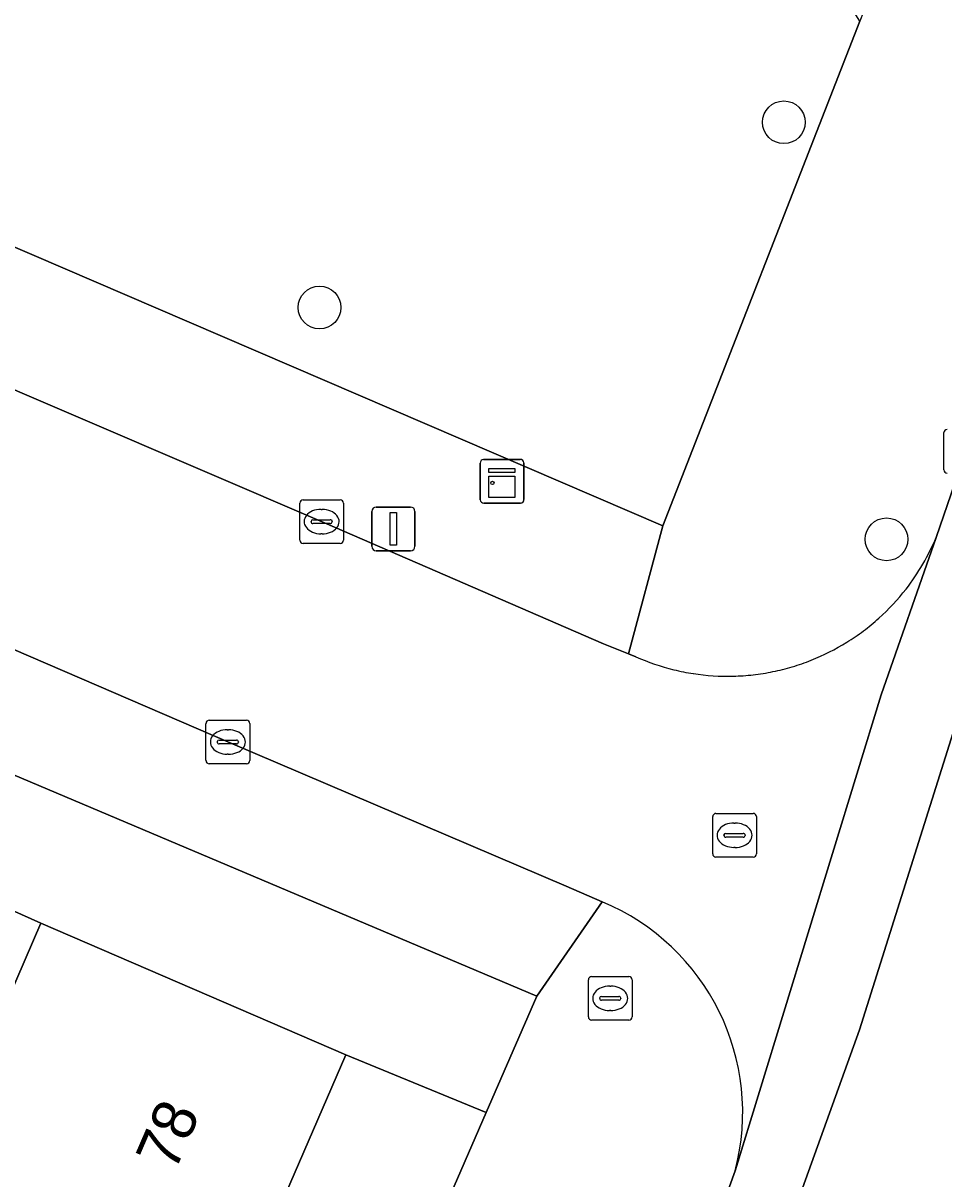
# Model space of a CAD drawing. Extents: x 162803 to 163818, y 381639 to 382475.
# Drawn here: x 163434.41 to 163455.49, y 382015.39 to 382041.86 of the extents above; entities that cross this region are included whole.
import ezdxf

# ---------------------------------------------------------------- set-up
doc = ezdxf.new("R2010")
doc.units = 0
for name, color, linetype in [('IMGEO_Boom', 7, 'Continuous'), ('IMGEO_Brandkraan', 7, 'Continuous'), ('IMGEO_Erf', 7, 'Continuous'), ('IMGEO_Groenvoorziening', 7, 'Continuous'), ('IMGEO_Haag', 7, 'Continuous'), ('IMGEO_Kast', 7, 'Continuous'), ('IMGEO_Kolk', 7, 'Continuous'), ('IMGEO_Lichtmast', 7, 'Continuous'), ('IMGEO_Pand', 7, 'Continuous'), ('IMGEO_Pand_nummerreeks', 7, 'Continuous'), ('IMGEO_Rijbaan_lokaal_gesloten', 7, 'Continuous'), ('IMGEO_Rijbaan_lokaal_open', 7, 'Continuous'), ('IMGEO_Rioolput', 7, 'Continuous'), ('IMGEO_Voetpad_open', 7, 'Continuous')]:
    doc.layers.add(name, color=color, linetype=linetype)

msp = doc.modelspace()

# ---------------------------------------------------------------- linework, layer by layer
at = {"layer": 'IMGEO_Boom'}
for centre in [(163451.822, 382039.591), (163441.195, 382035.351), (163454.174, 382030.04)]:
    msp.add_circle(centre, 0.489, dxfattribs=at)
at = {"layer": 'IMGEO_Brandkraan'}
for p, q in [((163447.348, 382019.102), (163447.348, 382019.954)), ((163447.423, 382020.028), (163448.275, 382020.028)), ((163448.349, 382019.954), (163448.349, 382019.102)), ((163447.836, 382019.808), (163447.861, 382019.808)), ((163447.607, 382019.522), (163447.607, 382019.534)), ((163448.045, 382019.485), (163447.647, 382019.485)), ((163447.65, 382019.571), (163448.048, 382019.571)), ((163448.091, 382019.534), (163448.091, 382019.522)), ((163447.859, 382019.248), (163447.834, 382019.248)), ((163448.275, 382019.028), (163447.423, 382019.028))]:
    msp.add_line(p, q, dxfattribs=at)
for points in [[(163447.348, 382019.102), (163447.348, 382019.954)], [(163447.423, 382020.028), (163448.275, 382020.028)], [(163448.349, 382019.954), (163448.349, 382019.102)], [(163448.275, 382019.028), (163447.423, 382019.028)]]:
    msp.add_lwpolyline(points, dxfattribs=at)
for centre, radius, start, end in [((163447.425, 382019.952), 0.0765, 91.552, 178.448), ((163447.425, 382019.952), 0.0765, 91.552, 178.448), ((163448.273, 382019.952), 0.0765, 1.552, 88.448), ((163448.273, 382019.952), 0.0765, 1.552, 88.448), ((163447.647, 382019.531), 0.0403, 85.8775, 175.7526), ((163447.644, 382019.521), 0.0366, 178.938, 274.7102), ((163448.048, 382019.528), 0.043, 264.8664, 352.4533), ((163448.052, 382019.533), 0.0386, 1.7309, 96.639), ((163447.425, 382019.104), 0.0765, 181.552, 268.448), ((163447.425, 382019.104), 0.0765, 181.552, 268.448), ((163448.273, 382019.104), 0.0765, 271.552, 358.448), ((163448.273, 382019.104), 0.0765, 271.552, 358.448)]:
    msp.add_arc(centre, radius, start, end, dxfattribs=at)
for centre, major_axis, ratio, start_param, end_param in [((163447.835, 382019.528), (-0.387, 0.002), 0.722429, 4.712389, 7.853982), ((163447.86, 382019.528), (-0.39, 0.002), 0.717154, 1.570796, 4.712389)]:
    msp.add_ellipse(centre, major_axis=major_axis, ratio=ratio, start_param=start_param, end_param=end_param, dxfattribs=at)
at = {"layer": 'IMGEO_Erf'}
for points in [[(163432.155, 382015.101), (163434.813, 382021.25), (163423.919, 382026.134)], [(163415.261, 381948.361), (163437.67, 382000), (163445.009, 382016.913), (163441.794, 382018.234), (163439.136, 382012.084), (163436.568, 382006.144), (163434.146, 382000.54)]]:
    msp.add_lwpolyline(points, dxfattribs=at)
at = {"layer": 'IMGEO_Groenvoorziening'}
for points in [[(163425.697, 382054.699), (163420.454, 382042.652), (163428.107, 382039.359), (163438.211, 382035.013), (163449.05, 382030.35), (163453.565, 382041.904), (163452.311, 382043.913), (163447.838, 382051.076), (163440.6, 382054.08), (163438.716, 382049.427), (163433.421, 382051.571)], [(163425.146, 382028.468), (163423.919, 382026.134), (163434.813, 382021.25), (163441.794, 382018.234), (163445.009, 382016.913), (163446.165, 382019.577)]]:
    msp.add_lwpolyline(points, close=True, dxfattribs=at)
at = {"layer": 'IMGEO_Haag'}
msp.add_lwpolyline([(163425.146, 382028.468), (163423.919, 382026.134), (163434.813, 382021.25), (163441.794, 382018.234), (163445.009, 382016.913), (163446.165, 382019.577)], close=True, dxfattribs=at)
at = {"layer": 'IMGEO_Kast'}
for p, q in [((163444.873, 382030.944), (163444.873, 382031.785)), ((163444.873, 382031.785), (163444.873, 382030.944)), ((163444.948, 382031.869), (163445.789, 382031.869)), ((163445.789, 382031.869), (163444.948, 382031.869)), ((163445.873, 382031.794), (163445.873, 382030.953)), ((163445.873, 382030.953), (163445.873, 382031.794)), ((163445.798, 382030.869), (163444.957, 382030.869)), ((163444.957, 382030.869), (163445.798, 382030.869))]:
    msp.add_line(p, q, dxfattribs=at)
for points in [[(163445.068, 382031.659), (163445.668, 382031.659), (163445.668, 382031.574), (163445.068, 382031.574), (163445.068, 382031.659)], [(163445.068, 382031.484), (163445.668, 382031.484), (163445.668, 382030.995), (163445.068, 382030.995), (163445.068, 382031.484)]]:
    msp.add_lwpolyline(points, dxfattribs=at)
msp.add_circle((163445.152, 382031.333), 0.0377, dxfattribs=at)
for centre, start, end in [((163444.951, 382031.791), 92.4484, 184.2845), ((163444.951, 382031.791), 92.4484, 184.2845), ((163445.795, 382031.791), 2.4484, 94.2845), ((163445.795, 382031.791), 2.4484, 94.2845), ((163444.951, 382030.947), 182.4484, 274.2845), ((163444.951, 382030.947), 182.4484, 274.2845), ((163445.795, 382030.947), 272.4484, 4.2845), ((163445.795, 382030.947), 272.4484, 4.2845)]:
    msp.add_arc(centre, 0.0779, start, end, dxfattribs=at)
at = {"layer": 'IMGEO_Kolk'}
for p, q in [((163455.486, 382031.631), (163455.486, 382032.483)), ((163440.741, 382030.02), (163440.741, 382030.872)), ((163440.816, 382030.946), (163441.668, 382030.946)), ((163441.229, 382030.726), (163441.254, 382030.726)), ((163441.742, 382030.872), (163441.742, 382030.02)), ((163441.043, 382030.489), (163441.441, 382030.489)), ((163441, 382030.44), (163441, 382030.452)), ((163441.438, 382030.403), (163441.04, 382030.403)), ((163441.484, 382030.452), (163441.484, 382030.44)), ((163441.668, 382029.946), (163440.816, 382029.946)), ((163441.252, 382030.166), (163441.227, 382030.166)), ((163438.595, 382024.973), (163438.595, 382025.825)), ((163438.67, 382025.899), (163439.522, 382025.899)), ((163439.596, 382025.825), (163439.596, 382024.973)), ((163438.897, 382025.442), (163439.295, 382025.442)), ((163439.083, 382025.679), (163439.108, 382025.679)), ((163438.854, 382025.393), (163438.854, 382025.405)), ((163439.292, 382025.356), (163438.894, 382025.356)), ((163439.338, 382025.405), (163439.338, 382025.393)), ((163439.522, 382024.899), (163438.67, 382024.899)), ((163439.106, 382025.119), (163439.081, 382025.119))]:
    msp.add_line(p, q, dxfattribs=at)
for points in [[(163455.486, 382031.631), (163455.486, 382032.483)], [(163440.741, 382030.02), (163440.741, 382030.872)], [(163440.816, 382030.946), (163441.668, 382030.946)], [(163441.742, 382030.872), (163441.742, 382030.02)], [(163441.668, 382029.946), (163440.816, 382029.946)], [(163438.595, 382024.973), (163438.595, 382025.825)], [(163438.67, 382025.899), (163439.522, 382025.899)], [(163439.596, 382025.825), (163439.596, 382024.973)], [(163439.522, 382024.899), (163438.67, 382024.899)]]:
    msp.add_lwpolyline(points, dxfattribs=at)
for centre, radius, start, end in [((163455.563, 382032.481), 0.0765, 91.552, 178.448), ((163455.563, 382032.481), 0.0765, 91.552, 178.448), ((163455.563, 382031.633), 0.0765, 181.552, 268.448), ((163455.563, 382031.633), 0.0765, 181.552, 268.448), ((163440.818, 382030.87), 0.0765, 91.552, 178.448), ((163440.818, 382030.87), 0.0765, 91.552, 178.448), ((163441.666, 382030.87), 0.0765, 1.552, 88.448), ((163441.666, 382030.87), 0.0765, 1.552, 88.448), ((163441.04, 382030.449), 0.0403, 85.8775, 175.7526), ((163441.445, 382030.451), 0.0386, 1.7309, 96.639), ((163441.037, 382030.439), 0.0366, 178.938, 274.7102), ((163441.441, 382030.446), 0.043, 264.8664, 352.4533), ((163440.818, 382030.022), 0.0765, 181.552, 268.448), ((163440.818, 382030.022), 0.0765, 181.552, 268.448), ((163441.666, 382030.022), 0.0765, 271.552, 358.448), ((163441.666, 382030.022), 0.0765, 271.552, 358.448), ((163438.672, 382025.823), 0.0765, 91.552, 178.448), ((163438.672, 382025.823), 0.0765, 91.552, 178.448), ((163439.52, 382025.823), 0.0765, 1.552, 88.448), ((163439.52, 382025.823), 0.0765, 1.552, 88.448), ((163438.894, 382025.402), 0.0403, 85.8775, 175.7526), ((163439.299, 382025.404), 0.0386, 1.7309, 96.639), ((163438.891, 382025.392), 0.0366, 178.938, 274.7102), ((163439.295, 382025.399), 0.043, 264.8664, 352.4533), ((163438.672, 382024.975), 0.0765, 181.552, 268.448), ((163438.672, 382024.975), 0.0765, 181.552, 268.448), ((163439.52, 382024.975), 0.0765, 271.552, 358.448), ((163439.52, 382024.975), 0.0765, 271.552, 358.448)]:
    msp.add_arc(centre, radius, start, end, dxfattribs=at)
for centre, major_axis, ratio, start_param, end_param in [((163441.228, 382030.446), (-0.387, 0.002), 0.722429, 4.712389, 7.853982), ((163441.253, 382030.446), (-0.39, 0.002), 0.717154, 1.570796, 4.712389), ((163439.082, 382025.399), (-0.387, 0.002), 0.722429, 4.712389, 7.853982), ((163439.107, 382025.399), (-0.39, 0.002), 0.717154, 1.570796, 4.712389)]:
    msp.add_ellipse(centre, major_axis=major_axis, ratio=ratio, start_param=start_param, end_param=end_param, dxfattribs=at)
at = {"layer": 'IMGEO_Lichtmast'}
for p, q in [((163442.489, 382030.78), (163443.279, 382030.78)), ((163443.279, 382030.78), (163442.489, 382030.78)), ((163442.389, 382029.88), (163442.389, 382030.68)), ((163442.389, 382030.68), (163442.389, 382029.88)), ((163443.379, 382030.68), (163443.379, 382029.88)), ((163443.379, 382029.88), (163443.379, 382030.68)), ((163443.279, 382029.78), (163442.489, 382029.78)), ((163442.489, 382029.78), (163443.279, 382029.78))]:
    msp.add_line(p, q, dxfattribs=at)
msp.add_lwpolyline([(163442.809, 382030.655), (163442.959, 382030.655), (163442.959, 382029.905), (163442.809, 382029.905), (163442.809, 382030.655)], dxfattribs=at)
for centre, start, end in [((163442.489, 382030.68), 90, 180), ((163442.489, 382030.68), 90, 180), ((163443.279, 382030.68), 0, 90), ((163443.279, 382030.68), 360, 90), ((163442.489, 382029.88), 180, 270), ((163442.489, 382029.88), 180, 270), ((163443.279, 382029.88), 270, 0), ((163443.279, 382029.88), 270, 0)]:
    msp.add_arc(centre, 0.1, start, end, dxfattribs=at)
at = {"layer": 'IMGEO_Pand'}
msp.add_lwpolyline([(163439.136, 382012.084), (163441.794, 382018.234), (163434.813, 382021.25), (163432.155, 382015.101)], close=True, dxfattribs=at)
at = {"layer": 'IMGEO_Rijbaan_lokaal_gesloten'}
for points in [[(163403.398, 381901.092), (163423.149, 381946.753), (163442.972, 381992.695), (163451.013, 382011.748), (163453.553, 382018.806), (163457.574, 382031.579), (163457.618, 382031.669), (163456.14, 382032.294), (163455.987, 382032.057), (163455.311, 382030.085), (163454.05, 382026.481), (163450.707, 382015.578), (163449.61, 382012.542), (163447.348, 382006.821), (163444.392, 382000), (163421.928, 381948.171), (163421.397, 381947.003), (163420.132, 381944.148), (163413.671, 381929.232), (163412.342, 381925.941)], [(163412.004, 381907.726), (163431.05, 381951.693), (163449.038, 381993.259), (163453.694, 382003.844), (163457.08, 382012.454), (163459.619, 382019.017), (163461.877, 382023.605), (163464.722, 382028.665), (163457.618, 382031.669), (163457.574, 382031.579), (163453.553, 382018.806), (163451.013, 382011.748), (163442.972, 381992.695), (163423.149, 381946.753), (163403.398, 381901.092)]]:
    msp.add_lwpolyline(points, dxfattribs=at)
at = {"layer": 'IMGEO_Rijbaan_lokaal_open'}
for points in [[(163415.894, 382041.32), (163409.601, 382044.051), (163407.444, 382039.08), (163413.933, 382036.26), (163439.148, 382025.378), (163446.837, 382022.1), (163447.666, 382021.737)], [(163448.437, 382027.35), (163448.265, 382027.42), (163447.698, 382027.649), (163441.305, 382030.418), (163415.894, 382041.32)], [(163450.707, 382015.578), (163454.05, 382026.481), (163455.311, 382030.085)]]:
    msp.add_lwpolyline(points, dxfattribs=at)
for centre, radius, start, end in [((163450.484, 382032.108), 5.234, 322.2288, 337.2643), ((163450.53, 382032.086), 5.184, 311.9695, 322.1024), ((163450.705, 382031.879), 4.913, 306.7395, 312.0687), ((163450.713, 382031.814), 4.856, 301.7141, 307.1227), ((163450.447, 382032.258), 5.374, 291.8772, 301.645), ((163450.583, 382032.209), 5.312, 246.1727, 256.0458), ((163450.453, 382031.684), 4.771, 256.0389, 261.5377), ((163450.657, 382031.616), 4.696, 281.2434, 286.8291), ((163450.64, 382031.784), 4.862, 286.4527, 291.8436), ((163450.538, 382032.043), 5.138, 261.1947, 271.4104), ((163450.528, 382032.13), 5.226, 271.4931, 276.5177), ((163450.539, 382032.047), 5.142, 276.4999, 281.6015), ((163445.657, 382016.915), 5.224, 345.1699, 67.3858)]:
    msp.add_arc(centre, radius, start, end, dxfattribs=at)
at = {"layer": 'IMGEO_Rioolput'}
for p, q in [((163450.194, 382022.837), (163450.194, 382023.689)), ((163450.269, 382023.763), (163451.121, 382023.763)), ((163451.195, 382023.689), (163451.195, 382022.837)), ((163450.682, 382023.543), (163450.707, 382023.543)), ((163450.453, 382023.257), (163450.453, 382023.269)), ((163450.891, 382023.22), (163450.493, 382023.22)), ((163450.496, 382023.306), (163450.894, 382023.306)), ((163450.937, 382023.269), (163450.937, 382023.257)), ((163450.705, 382022.983), (163450.68, 382022.983)), ((163451.121, 382022.763), (163450.269, 382022.763))]:
    msp.add_line(p, q, dxfattribs=at)
for points in [[(163450.194, 382022.837), (163450.194, 382023.689)], [(163450.269, 382023.763), (163451.121, 382023.763)], [(163451.195, 382023.689), (163451.195, 382022.837)], [(163451.121, 382022.763), (163450.269, 382022.763)]]:
    msp.add_lwpolyline(points, dxfattribs=at)
for centre, radius, start, end in [((163450.271, 382023.687), 0.0765, 91.552, 178.448), ((163450.271, 382023.687), 0.0765, 91.552, 178.448), ((163451.119, 382023.687), 0.0765, 1.552, 88.448), ((163451.119, 382023.687), 0.0765, 1.552, 88.448), ((163450.493, 382023.266), 0.0403, 85.8775, 175.7526), ((163450.49, 382023.256), 0.0366, 178.938, 274.7102), ((163450.894, 382023.263), 0.043, 264.8664, 352.4533), ((163450.898, 382023.268), 0.0386, 1.7309, 96.639), ((163450.271, 382022.839), 0.0765, 181.552, 268.448), ((163450.271, 382022.839), 0.0765, 181.552, 268.448), ((163451.119, 382022.839), 0.0765, 271.552, 358.448), ((163451.119, 382022.839), 0.0765, 271.552, 358.448)]:
    msp.add_arc(centre, radius, start, end, dxfattribs=at)
for centre, major_axis, ratio, start_param, end_param in [((163450.681, 382023.263), (-0.387, 0.002), 0.722429, 4.712389, 7.853982), ((163450.706, 382023.263), (-0.39, 0.002), 0.717154, 1.570796, 4.712389)]:
    msp.add_ellipse(centre, major_axis=major_axis, ratio=ratio, start_param=start_param, end_param=end_param, dxfattribs=at)
at = {"layer": 'IMGEO_Voetpad_open'}
for points in [[(163475.976, 382107.721), (163474.584, 382103.417), (163472.395, 382096.577), (163466.551, 382078.26), (163467.108, 382078.091), (163465.926, 382074.365), (163465.365, 382074.542), (163461.545, 382062.564), (163461.119, 382061.247), (163460.409, 382059.416), (163455.894, 382047.864), (163454.487, 382044.265), (163453.565, 382041.904), (163449.05, 382030.35), (163448.265, 382027.42), (163448.437, 382027.35)], [(163455.311, 382030.085), (163455.987, 382032.057), (163456.14, 382032.294), (163460.098, 382041.653), (163460.465, 382042.582), (163460.478, 382043.225), (163459.637, 382045.069), (163459.622, 382045.107), (163459.608, 382045.146), (163459.596, 382045.186), (163459.586, 382045.226), (163459.578, 382045.266), (163459.571, 382045.307), (163459.567, 382045.348), (163459.563, 382045.471), (163459.565, 382045.512), (163459.569, 382045.553), (163459.575, 382045.594), (163459.583, 382045.635)], [(163409.231, 382044.212), (163409.601, 382044.051), (163415.894, 382041.32), (163441.305, 382030.418), (163447.698, 382027.649), (163448.265, 382027.42), (163449.05, 382030.35), (163438.211, 382035.013), (163428.107, 382039.359)], [(163404.112, 382040.424), (163402.515, 382036.752), (163402.669, 382036.714), (163404.617, 382037.351), (163404.69, 382037.496), (163406.543, 382036.647), (163423.891, 382029.027), (163425.146, 382028.468), (163446.165, 382019.577), (163447.666, 382021.737), (163446.837, 382022.1), (163439.148, 382025.378), (163413.933, 382036.26)], [(163447.666, 382021.737), (163446.165, 382019.577), (163445.009, 382016.913), (163437.67, 382000), (163415.261, 381948.361), (163414.525, 381946.665), (163414.224, 381941.814)], [(163442.21, 382000), (163446.924, 382010.886), (163447.467, 382011.45), (163449.61, 382012.542), (163450.707, 382015.578)]]:
    msp.add_lwpolyline(points, dxfattribs=at)
for centre, radius, start, end in [((163450.484, 382032.108), 5.234, 322.2288, 337.2643), ((163450.53, 382032.086), 5.184, 311.9695, 322.1024), ((163450.705, 382031.879), 4.913, 306.7395, 312.0687), ((163450.713, 382031.814), 4.856, 301.7141, 307.1227), ((163450.447, 382032.258), 5.374, 291.8772, 301.645), ((163450.583, 382032.209), 5.312, 246.1727, 256.0458), ((163450.453, 382031.684), 4.771, 256.0389, 261.5377), ((163450.657, 382031.616), 4.696, 281.2434, 286.8291), ((163450.64, 382031.784), 4.862, 286.4527, 291.8436), ((163450.538, 382032.043), 5.138, 261.1947, 271.4104), ((163450.528, 382032.13), 5.226, 271.4931, 276.5177), ((163450.539, 382032.047), 5.142, 276.4999, 281.6015), ((163445.657, 382016.915), 5.224, 345.1699, 67.3858)]:
    msp.add_arc(centre, radius, start, end, dxfattribs=at)

# ---------------------------------------------------------------- texts
at = {"layer": 'IMGEO_Pand_nummerreeks'}
msp.add_text('78', height=1, rotation=66.6226, dxfattribs=at).set_placement((163437.879, 382015.529))

doc.saveas('drawing.dxf')
